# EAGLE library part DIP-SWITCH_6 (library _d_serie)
DIP-Switch 6-fach
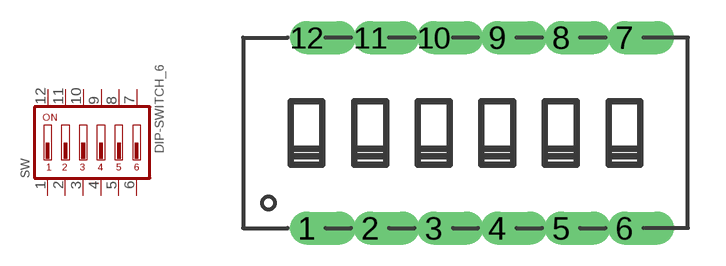
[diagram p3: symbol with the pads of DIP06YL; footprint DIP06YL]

Designator prefix SW

## DIP-SWITCH_6  [DIP06YL]
1  1  pas
2  2  pas
3  3  pas
4  4  pas
5  5  pas
6  6  pas
7  7  pas
8  8  pas
9  9  pas
10  10  pas
11  11  pas
12  12  pas

## Footprint DIP06YL (pad centres in mm)
DIP-Switch 6-fach
drill 0.813 offset: 1 -6.35,-3.81; 2 -3.81,-3.81; 3 -1.27,-3.81; 4 1.27,-3.81; 5 3.81,-3.81; 6 6.35,-3.81; 7 6.35,3.81; 8 3.81,3.81; 9 1.27,3.81; 10 -1.27,3.81; 11 -3.81,3.81; 12 -6.35,3.81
